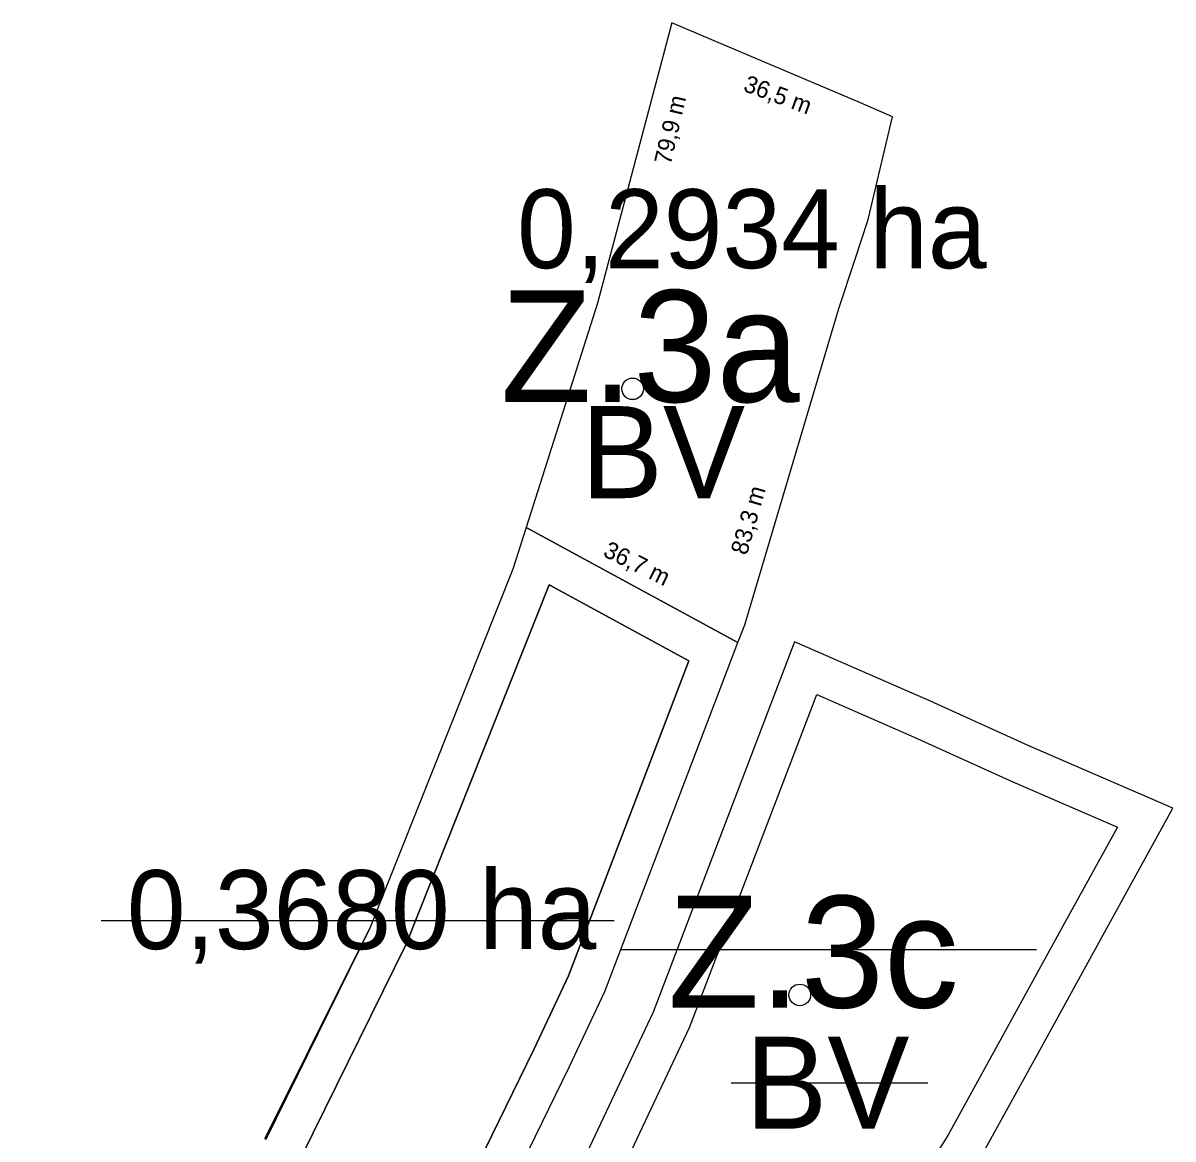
# Model space of a CAD drawing. Extents: x -554894 to -553703, y -1185789 to -1185042.
# Drawn here: x -554805.8 to -554631, y -1185211.3 to -1185041.6 of the extents above; entities that cross this region are included whole.
import ezdxf

# ---------------------------------------------------------------- set-up
doc = ezdxf.new("R2010")
doc.units = 0
for name, color, linetype in [('BILA_TECKA', 7, 'Continuous'), ('ID_navrh', 7, 'Continuous'), ('KRIZEK_ke_zruseni', 7, 'Continuous'), ('LEG_prac_vykres_ZPF', 7, 'Continuous'), ('navrh_BV', 7, 'Continuous'), ('OBRYS_PLOCH', 7, 'Continuous'), ('REGULATIV_navrh', 7, 'Continuous'), ('rezerva_BV', 7, 'Continuous'), ('upusteno_platny_UP', 7, 'Continuous'), ('upusteno_zmena_1', 7, 'Continuous'), ('vymery', 7, 'Continuous'), ('ZASTAVITELNA_PLOCHA', 7, 'Continuous')]:
    doc.layers.add(name, color=color, linetype=linetype)

msp = doc.modelspace()

# ---------------------------------------------------------------- linework, layer by layer
at = {"layer": 'BILA_TECKA'}
for centre in [(-554713.12, -1185097.19), (-554687.71, -1185189.37)]:
    msp.add_circle(centre, 1.64, dxfattribs=at)
at = {"layer": 'KRIZEK_ke_zruseni'}
for p, q in [((-554714.98, -1185182.44), (-554651.7, -1185182.44)), ((-554698.12, -1185202.76), (-554668.25, -1185202.76))]:
    msp.add_line(p, q, dxfattribs=at)
at = {"layer": 'LEG_prac_vykres_ZPF'}
msp.add_lwpolyline([(-554741.6, -1185226.21), (-554738.8, -1185219.49), (-554728.14, -1185197.66), (-554722.87, -1185186.48), (-554704.58, -1185138.55), (-554725.82, -1185127.02), (-554747.57, -1185181.64), (-554763.45, -1185213.94), (-554777.88, -1185244.55), (-554805.8, -1185298.3), (-554783.85, -1185310.28), (-554755.47, -1185255.65), (-554741.6, -1185226.21)], dxfattribs=at)
at = {"layer": 'navrh_BV'}
for p, q in [((-554707.18, -1185041.55), (-554718.48, -1185084.14)), ((-554673.61, -1185055.83), (-554678.5, -1185053.7)), ((-554674.57, -1185059.86), (-554673.61, -1185055.83)), ((-554677.33, -1185071.44), (-554674.57, -1185059.86)), ((-554679.31, -1185077.48), (-554677.33, -1185071.44)), ((-554681.76, -1185084.97), (-554679.31, -1185077.48)), ((-554718.48, -1185084.14), (-554729.32, -1185118.29)), ((-554696.07, -1185133.1), (-554681.76, -1185084.97)), ((-554729.32, -1185118.29), (-554697.1, -1185135.79)), ((-554697.1, -1185135.79), (-554696.07, -1185133.1))]:
    msp.add_line(p, q, dxfattribs=at)
msp.add_lwpolyline([(-554678.5, -1185053.7), (-554699.04, -1185044.99), (-554707.18, -1185041.55)], dxfattribs=at)
at = {"layer": 'OBRYS_PLOCH'}
for p, q in [((-554707.18, -1185041.55), (-554718.48, -1185084.14)), ((-554673.61, -1185055.83), (-554678.5, -1185053.7)), ((-554674.57, -1185059.86), (-554673.61, -1185055.83)), ((-554677.33, -1185071.44), (-554674.57, -1185059.86)), ((-554679.31, -1185077.48), (-554677.33, -1185071.44)), ((-554681.76, -1185084.97), (-554679.31, -1185077.48)), ((-554718.48, -1185084.14), (-554729.32, -1185118.29)), ((-554696.07, -1185133.1), (-554681.76, -1185084.97)), ((-554729.32, -1185118.29), (-554697.1, -1185135.79)), ((-554697.1, -1185135.79), (-554696.07, -1185133.1))]:
    msp.add_line(p, q, dxfattribs=at)
msp.add_lwpolyline([(-554678.5, -1185053.7), (-554699.04, -1185044.99), (-554707.18, -1185041.55)], dxfattribs=at)
at = {"layer": 'rezerva_BV'}
for p, q in [((-554729.32, -1185118.29), (-554731.33, -1185124.63)), ((-554697.1, -1185135.79), (-554729.32, -1185118.29)), ((-554731.33, -1185124.63), (-554753.06, -1185179.2)), ((-554717.35, -1185188.83), (-554697.1, -1185135.79)), ((-554688.49, -1185135.67), (-554709.98, -1185191.97)), ((-554667.86, -1185144.71), (-554688.49, -1185135.67)), ((-554704.46, -1185194.32), (-554685.13, -1185143.69)), ((-554685.13, -1185143.69), (-554670.3, -1185150.19)), ((-554652.87, -1185151.49), (-554667.86, -1185144.71)), ((-554670.3, -1185150.19), (-554655.3, -1185156.98)), ((-554630.97, -1185160.97), (-554652.87, -1185151.49)), ((-554641.88, -1185180.77), (-554630.97, -1185160.97)), ((-554753.06, -1185179.2), (-554768.86, -1185211.34)), ((-554651.54, -1185198.32), (-554641.88, -1185180.77)), ((-554722.73, -1185200.26), (-554717.35, -1185188.83)), ((-554709.98, -1185191.97), (-554738.91, -1185253.34)), ((-554660.04, -1185213.75), (-554651.54, -1185198.32)), ((-554733.33, -1185221.96), (-554722.73, -1185200.26))]:
    msp.add_line(p, q, dxfattribs=at)
for points in [[(-554755.47, -1185255.65), (-554783.85, -1185310.28), (-554805.8, -1185298.3), (-554777.88, -1185244.55), (-554763.45, -1185213.94), (-554747.57, -1185181.64), (-554725.82, -1185127.02), (-554704.58, -1185138.55), (-554722.87, -1185186.48), (-554728.14, -1185197.66), (-554738.8, -1185219.49), (-554741.6, -1185226.21), (-554755.47, -1185255.65)], [(-554655.3, -1185156.98), (-554639.41, -1185163.85), (-554647.14, -1185177.88), (-554656.8, -1185195.43), (-554665.22, -1185210.73), (-554666.42, -1185212.66), (-554687.53, -1185246.82)], [(-554766.29, -1185319.86), (-554737.54, -1185264.52), (-554704.46, -1185194.32)]]:
    msp.add_lwpolyline(points, dxfattribs=at)
at = {"layer": 'upusteno_platny_UP'}
for p, q in [((-554729.32, -1185118.29), (-554731.33, -1185124.63)), ((-554697.1, -1185135.79), (-554729.32, -1185118.29)), ((-554731.33, -1185124.63), (-554753.06, -1185179.2)), ((-554717.35, -1185188.83), (-554697.1, -1185135.79)), ((-554722.73, -1185200.26), (-554717.35, -1185188.83)), ((-554733.33, -1185221.96), (-554722.73, -1185200.26)), ((-554769.05, -1185211.23), (-554768.86, -1185211.34))]:
    msp.add_line(p, q, dxfattribs=at)
msp.add_lwpolyline([(-554753.06, -1185179.2), (-554755.68, -1185184.45), (-554769.05, -1185211.23)], dxfattribs=at)
at = {"layer": 'upusteno_zmena_1'}
for p, q in [((-554688.49, -1185135.67), (-554709.98, -1185191.97)), ((-554667.86, -1185144.71), (-554688.49, -1185135.67)), ((-554652.87, -1185151.49), (-554667.86, -1185144.71)), ((-554630.97, -1185160.97), (-554652.87, -1185151.49)), ((-554641.88, -1185180.77), (-554630.97, -1185160.97)), ((-554651.54, -1185198.32), (-554641.88, -1185180.77)), ((-554709.98, -1185191.97), (-554738.91, -1185253.34)), ((-554660.04, -1185213.75), (-554651.54, -1185198.32))]:
    msp.add_line(p, q, dxfattribs=at)
at = {"layer": 'vymery'}
msp.add_lwpolyline([(-554793.93, -1185178.05), (-554793.93, -1185178.05), (-554715.94, -1185178.05)], dxfattribs=at)
at = {"layer": 'ZASTAVITELNA_PLOCHA'}
for p, q in [((-554707.18, -1185041.55), (-554718.48, -1185084.14)), ((-554673.61, -1185055.83), (-554678.5, -1185053.7)), ((-554674.57, -1185059.86), (-554673.61, -1185055.83)), ((-554677.33, -1185071.44), (-554674.57, -1185059.86)), ((-554679.31, -1185077.48), (-554677.33, -1185071.44)), ((-554681.76, -1185084.97), (-554679.31, -1185077.48)), ((-554718.48, -1185084.14), (-554729.32, -1185118.29)), ((-554696.07, -1185133.1), (-554681.76, -1185084.97)), ((-554729.32, -1185118.29), (-554697.1, -1185135.79)), ((-554697.1, -1185135.79), (-554696.07, -1185133.1))]:
    msp.add_line(p, q, dxfattribs=at)
msp.add_lwpolyline([(-554678.5, -1185053.7), (-554699.04, -1185044.99), (-554707.18, -1185041.55)], dxfattribs=at)

# ---------------------------------------------------------------- texts
at = {"layer": 'ID_navrh'}
for s, p in [('Z.3a', (-554733.21, -1185099.19)), ('Z.3c', (-554707.76, -1185191.3))]:
    msp.add_text(s, height=17, dxfattribs=at).set_placement(p)
at = {"layer": 'REGULATIV_navrh'}
for p in [(-554721, -1185113.82), (-554696.01, -1185209.72)]:
    msp.add_text('BV', height=14, dxfattribs=at).set_placement(p)
at = {"layer": 'vymery'}
for s, rotation, p in [('36,5 m', 339.803, (-554696.44, -1185051.84)), ('79,9 m', 77.0218, (-554707.34, -1185063.22)), ('83,3 m', 73.9725, (-554695.77, -1185122.6)), ('36,7 m', 333.8757, (-554717.77, -1185122.57))]:
    msp.add_text(s, height=2.592, rotation=rotation, dxfattribs=at).set_placement(p)
for s, p in [('0,2934 ha', (-554730.69, -1185078.84)), ('0,3680 ha', (-554790.01, -1185182.4))]:
    msp.add_text(s, height=12, dxfattribs=at).set_placement(p)

doc.saveas('drawing.dxf')
